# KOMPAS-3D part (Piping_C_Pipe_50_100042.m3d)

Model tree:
1. Plane XY
2. Plane ZX
3. Plane ZY
4. X Axis
5. Y Axis
6. Z Axis
7. Origin
8. Path  (labels: Труба Dy 50; Тройник Dy 50)
9. Plane of section
10. Section of pipe
11. Pipe
     Толщина стенки 1 = 1

Referenced files in C:\Program Files\ASCON\KOMPAS-3D V10\Libs\Piping\Models\Tanks\: Tanks.a3d
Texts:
  Pipe Dn 50
  Steel ASTM A295
  Three Point Plane
  Plane at Angle
  Line and Point Plane
  Axis through Two Vertices
  Axis of Feature
  Axis of Conical Surface
  Axis through Edge
  Приклеить элемент выдавливания
  Приклеить элемент вращения
  Приклеить кинематический элемент
  Приклеить элемент по сечениям
  Trim by Surface
  Trim by Sketch
  Feature with No History
  Intersection Axis of Two Planes
  Two Line Plane
  Line and Face Plane
  Bend by line
  Hole in sheet body
  Cut in sheet body
  Point in CM
  Linear Dimension from Line to Point
  Surface Finish Symbol
  Geometric Tolerance Symbol
  Текст на чертеже
  Линия-выноска #1
  Линия-выноска #2
  Линия-выноска #3
  Отклонения формы и база
  Марка координационной оси
  Марка/позиционное обозначение с линией-выноской
  Марка/позиционное обозначение на линии
  Марка/позиционное обозначение без линии-выноски
  Труба Dy 50
  Тройник Dy 50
